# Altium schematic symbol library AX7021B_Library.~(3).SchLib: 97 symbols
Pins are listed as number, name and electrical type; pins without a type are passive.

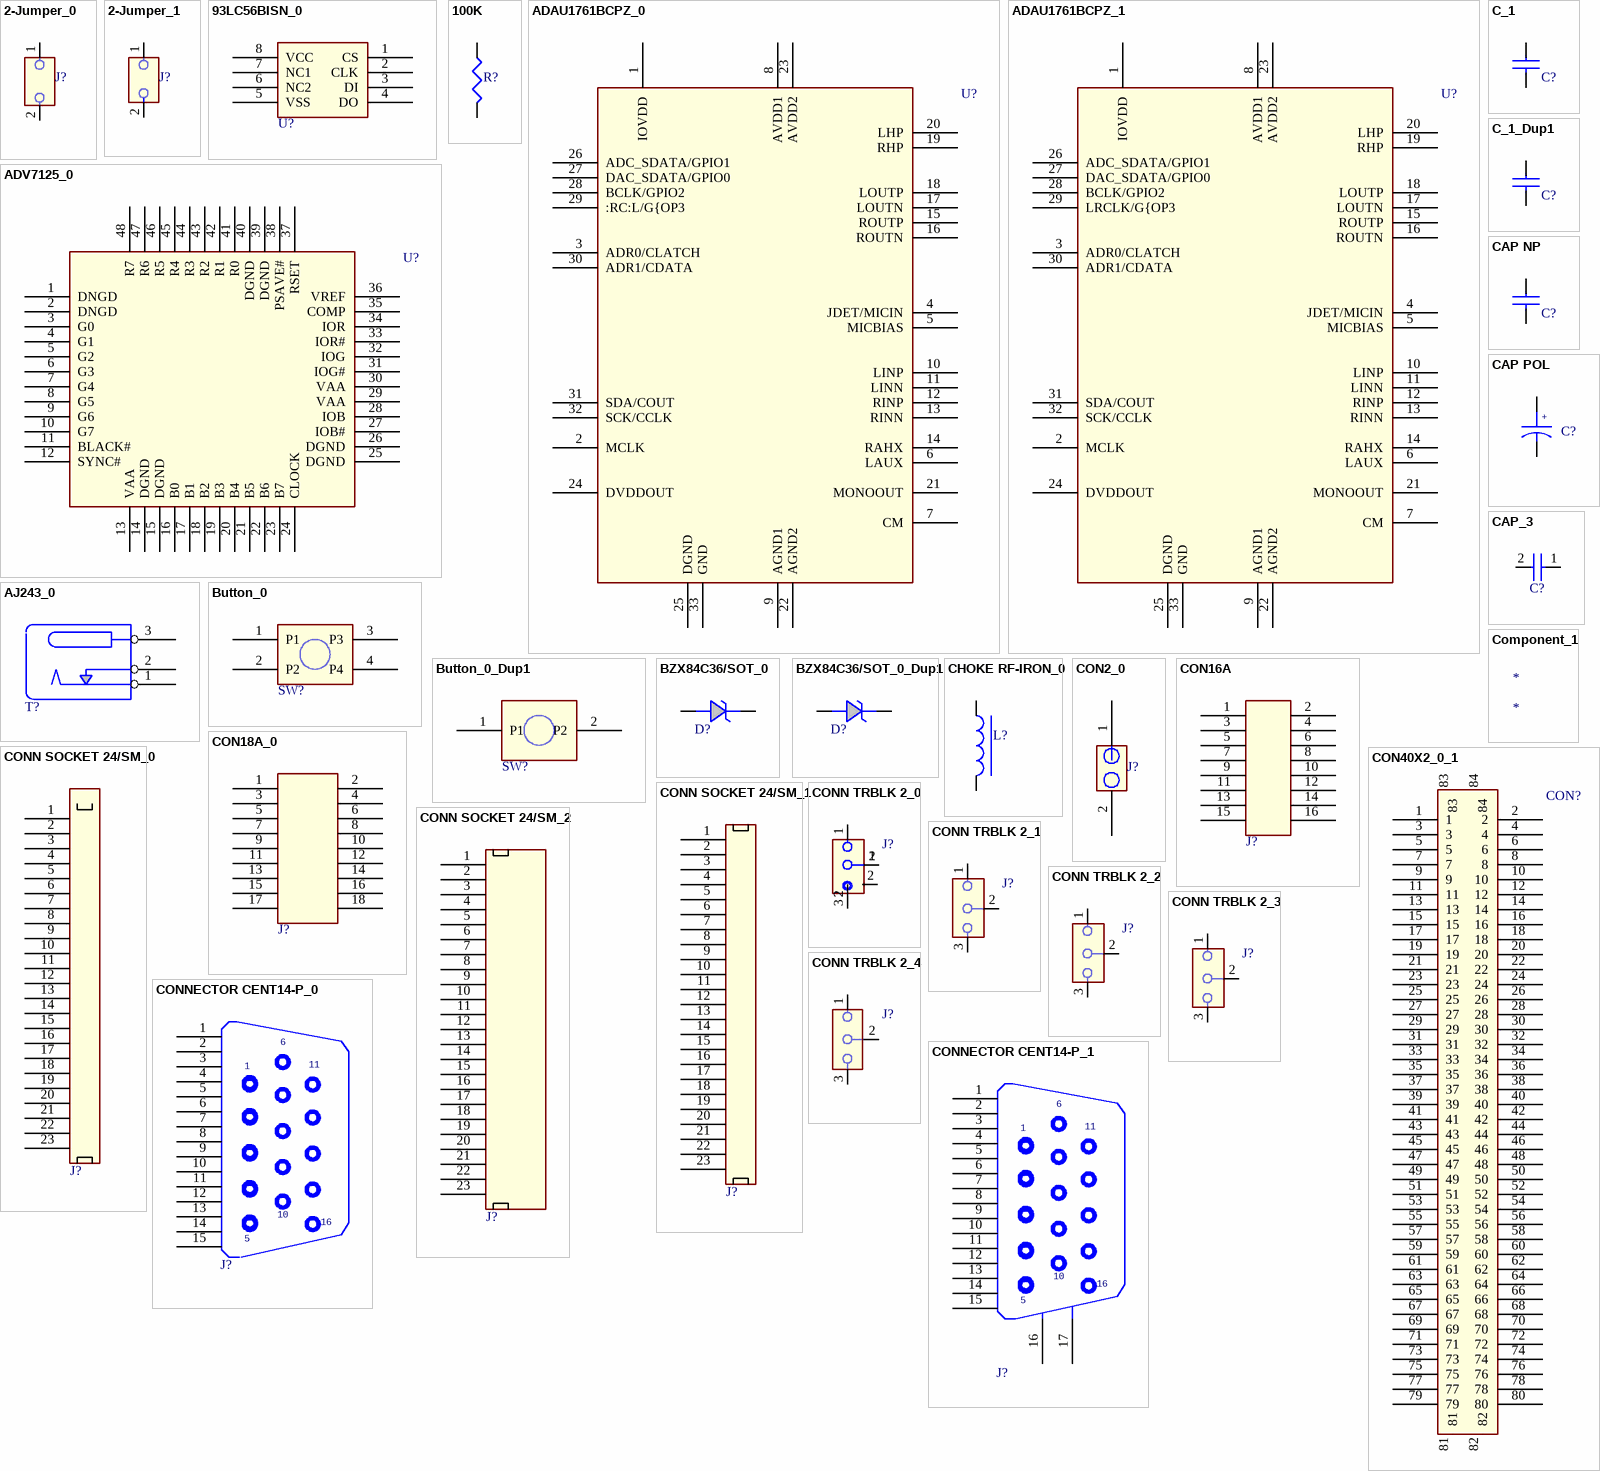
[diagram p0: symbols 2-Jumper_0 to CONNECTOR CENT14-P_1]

## 2-Jumper_0
designator J?
Altium-Right: 20; Altium-Bottom: 32
footprint 2-Jumper
pins: 1, 2

## 2-Jumper_1
designator J?
Altium-Right: 20; Altium-Bottom: 30
footprint 2-Jumper
pins: 1, 2

## 93LC56BISN_0
designator U?
Altium-Right: 60; Altium-Bottom: 50
pins: 1 CS, 2 CLK, 3 DI, 4 DO, 5 VSS, 6 NC2, 7 NC1, 8 VCC

## 100K
designator R?
5%; Part Number: RC0402JR-07100KL; Manufacturer: YAGEO; Altium-Right: 20; Altium-Bottom: 30
footprint R0402
pins: 1, 2

## ADAU1761BCPZ_0
designator U?
Altium-Right: 210; Altium-Bottom: 330
pins: 1 IOVDD, 2 MCLK, 3 ADR0/CLATCH, 4 JDET/MICIN, 5 MICBIAS, 6 LAUX, 7 CM, 8 AVDD1, 9 AGND1, 10 LINP, 11 LINN, 12 RINP, 13 RINN, 14 RAHX, 15 ROUTP, 16 ROUTN, 17 LOUTN, 18 LOUTP, 19 RHP, 20 LHP, 21 MONOOUT, 22 AGND2, 23 AVDD2, 24 DVDDOUT, 25 DGND, 26 ADC_SDATA/GPIO1, 27 DAC_SDATA/GPIO0, 28 BCLK/GPIO2, 29 :RC:L/G{OP3, 30 ADR1/CDATA, 31 SDA/COUT, 32 SCK/CCLK, 33 GND

## ADAU1761BCPZ_1
designator U?
Altium-Right: 210; Altium-Bottom: 330
pins: 1 IOVDD, 2 MCLK, 3 ADR0/CLATCH, 4 JDET/MICIN, 5 MICBIAS, 6 LAUX, 7 CM, 8 AVDD1, 9 AGND1, 10 LINP, 11 LINN, 12 RINP, 13 RINN, 14 RAHX, 15 ROUTP, 16 ROUTN, 17 LOUTN, 18 LOUTP, 19 RHP, 20 LHP, 21 MONOOUT, 22 AGND2, 23 AVDD2, 24 DVDDOUT, 25 DGND, 26 ADC_SDATA/GPIO1, 27 DAC_SDATA/GPIO0, 28 BCLK/GPIO2, 29 LRCLK/G{OP3, 30 ADR1/CDATA, 31 SDA/COUT, 32 SCK/CCLK, 33 GND

## ADV7125_0
designator U?
Altium-Right: 190; Altium-Bottom: 170
footprint LQFP-48
pins: 1 DNGD, 2 DNGD, 3 G0, 4 G1, 5 G2, 6 G3, 7 G4, 8 G5, 9 G6, 10 G7, 11 BLACK#, 12 SYNC#, 13 VAA, 14 DGND, 15 DGND, 16 B0, 17 B1, 18 B2, 19 B3, 20 B4, 21 B5, 22 B6, 23 B7, 24 CLOCK, 25 DGND, 26 DGND, 27 IOB#, 28 IOB, 29 VAA, 30 VAA, 31 IOG#, 32 IOG, 33 IOR#, 34 IOR, 35 COMP, 36 VREF, 37 RSET, 38 PSAVE#, 39 DGND, 40 DGND, 41 R0, 42 R1, 43 R2, 44 R3, 45 R4, 46 R5, 47 R6, 48 R7

## AJ243_0
designator T?
Altium-Right: 70; Altium-Bottom: 50
pins: 1, 2, 3

## Button_0
designator SW?
Altium-Right: 50; Altium-Bottom: 40
pins: 1 P1, 2 P2, 3 P3, 4 P4

## Button_0_Dup1
designator SW?
Altium-Right: 50; Altium-Bottom: 40
pins: 1 P1, 2 P2

## BZX84C36/SOT_0
designator D?
Altium-Right: 30; Altium-Bottom: 20
pins: 1 CATHODE, 2 ANODE

## BZX84C36/SOT_0_Dup1
designator D?
Altium-Right: 30; Altium-Bottom: 20
pins: 1 CATHODE, 2 ANODE

## C_1
designator C?
Altium-Right: 20; Altium-Bottom: 10
pins: 1, 2

## C_1_Dup1
designator C?
Altium-Right: 20; Altium-Bottom: 10
pins: 1, 2

## CAP NP
designator C?
Altium-Right: 20; Altium-Bottom: 10
pins: 1, 2

## CAP POL
designator C?
Altium-Right: 20
pins: 1, 2

## CAP_3
designator C?
Altium-Right: 10; Altium-Bottom: 20
pins: 1, 2

## CHOKE RF-IRON_0
designator L?
Altium-Right: 10; Altium-Bottom: 40
pins: 1, 2

## Component_1
designator *

## CON2_0
designator J?
Altium-Right: 20; Altium-Bottom: 30
pins: 1, 2

## CON16A
designator J?
Altium-Right: 30; Altium-Bottom: 90
pins: 1, 2, 3, 4, 5, 6, 7, 8, 9, 10, 11, 12, 13, 14, 15, 16

## CON18A_0
designator J?
Altium-Right: 40; Altium-Bottom: 100
pins: 1, 2, 3, 4, 5, 6, 7, 8, 9, 10, 11, 12, 13, 14, 15, 16, 17, 18

## CON40X2_0_1
designator CON?
Altium-Right: 40; Altium-Bottom: 430
footprint CON40X2_0_8MM
pins: 1, 2, 3, 4, 5, 6, 7, 8, 9, 10, 11, 12, 13, 14, 15, 16, 17, 18, 19, 20, 21, 22, 23, 24, 25, 26, 27, 28, 29, 30, 31, 32, 33, 34, 35, 36, 37, 38, 39, 40, 41, 42, 43, 44, 45, 46, 47, 48, 49, 50, 51, 52, 53, 54, 55, 56, 57, 58, 59, 60, 61, 62, 63, 64, 65, 66, 67, 68, 69, 70, 71, 72, 73, 74, 75, 76, 77, 78, 79, 80, 81, 82, 83, 84

## CONN SOCKET 24/SM_0
designator J?
Altium-Right: 20; Altium-Bottom: 250
pins: 1, 2, 3, 4, 5, 6, 7, 8, 9, 10, 11, 12, 13, 14, 15, 16, 17, 18, 19, 20, 21, 22, 23

## CONN SOCKET 24/SM_1
designator J?
Altium-Right: 20; Altium-Bottom: 240
pins: 1, 2, 3, 4, 5, 6, 7, 8, 9, 10, 11, 12, 13, 14, 15, 16, 17, 18, 19, 20, 21, 22, 23

## CONN SOCKET 24/SM_2
designator J?
Altium-Right: 40; Altium-Bottom: 240
pins: 1 NC, 2 VSS, 3 VDD, 4 VDDIO, 5 BS1, 6 BS2, 7 IREF, 8 CS#, 9 RES#, 10 D/C#, 11 R/W#, 12 E(RD#), 13 D0, 14 D1, 15 D2, 16 D3, 17 D4, 18 D5, 19 D6, 20 D7, 21 VCOMH, 22 VCC, 23

## CONN TRBLK 2_0
designator J?
Altium-Right: 21; Altium-Bottom: 36
pins: 1, 1, 2, 2, 2, 2, 3

## CONN TRBLK 2_1
designator J?
Altium-Right: 21; Altium-Bottom: 39
pins: 1, 2, 3

## CONN TRBLK 2_2
designator J?
Altium-Right: 21; Altium-Bottom: 39
pins: 1, 2, 3

## CONN TRBLK 2_3
designator J?
Altium-Right: 21; Altium-Bottom: 39
pins: 1, 2, 3

## CONN TRBLK 2_4
designator J?
Altium-Right: 21; Altium-Bottom: 40
pins: 1, 2, 3

## CONNECTOR CENT14-P_0
designator J?
Altium-Right: 86; Altium-Bottom: 157
pins: 1, 2, 3, 4, 5, 6, 7, 8, 9, 10, 11, 12, 13, 14, 15

## CONNECTOR CENT14-P_1
designator J?
Altium-Right: 86; Altium-Bottom: 157
pins: 1, 2, 3, 4, 5, 6, 7, 8, 9, 10, 11, 12, 13, 14, 15, 16, 17

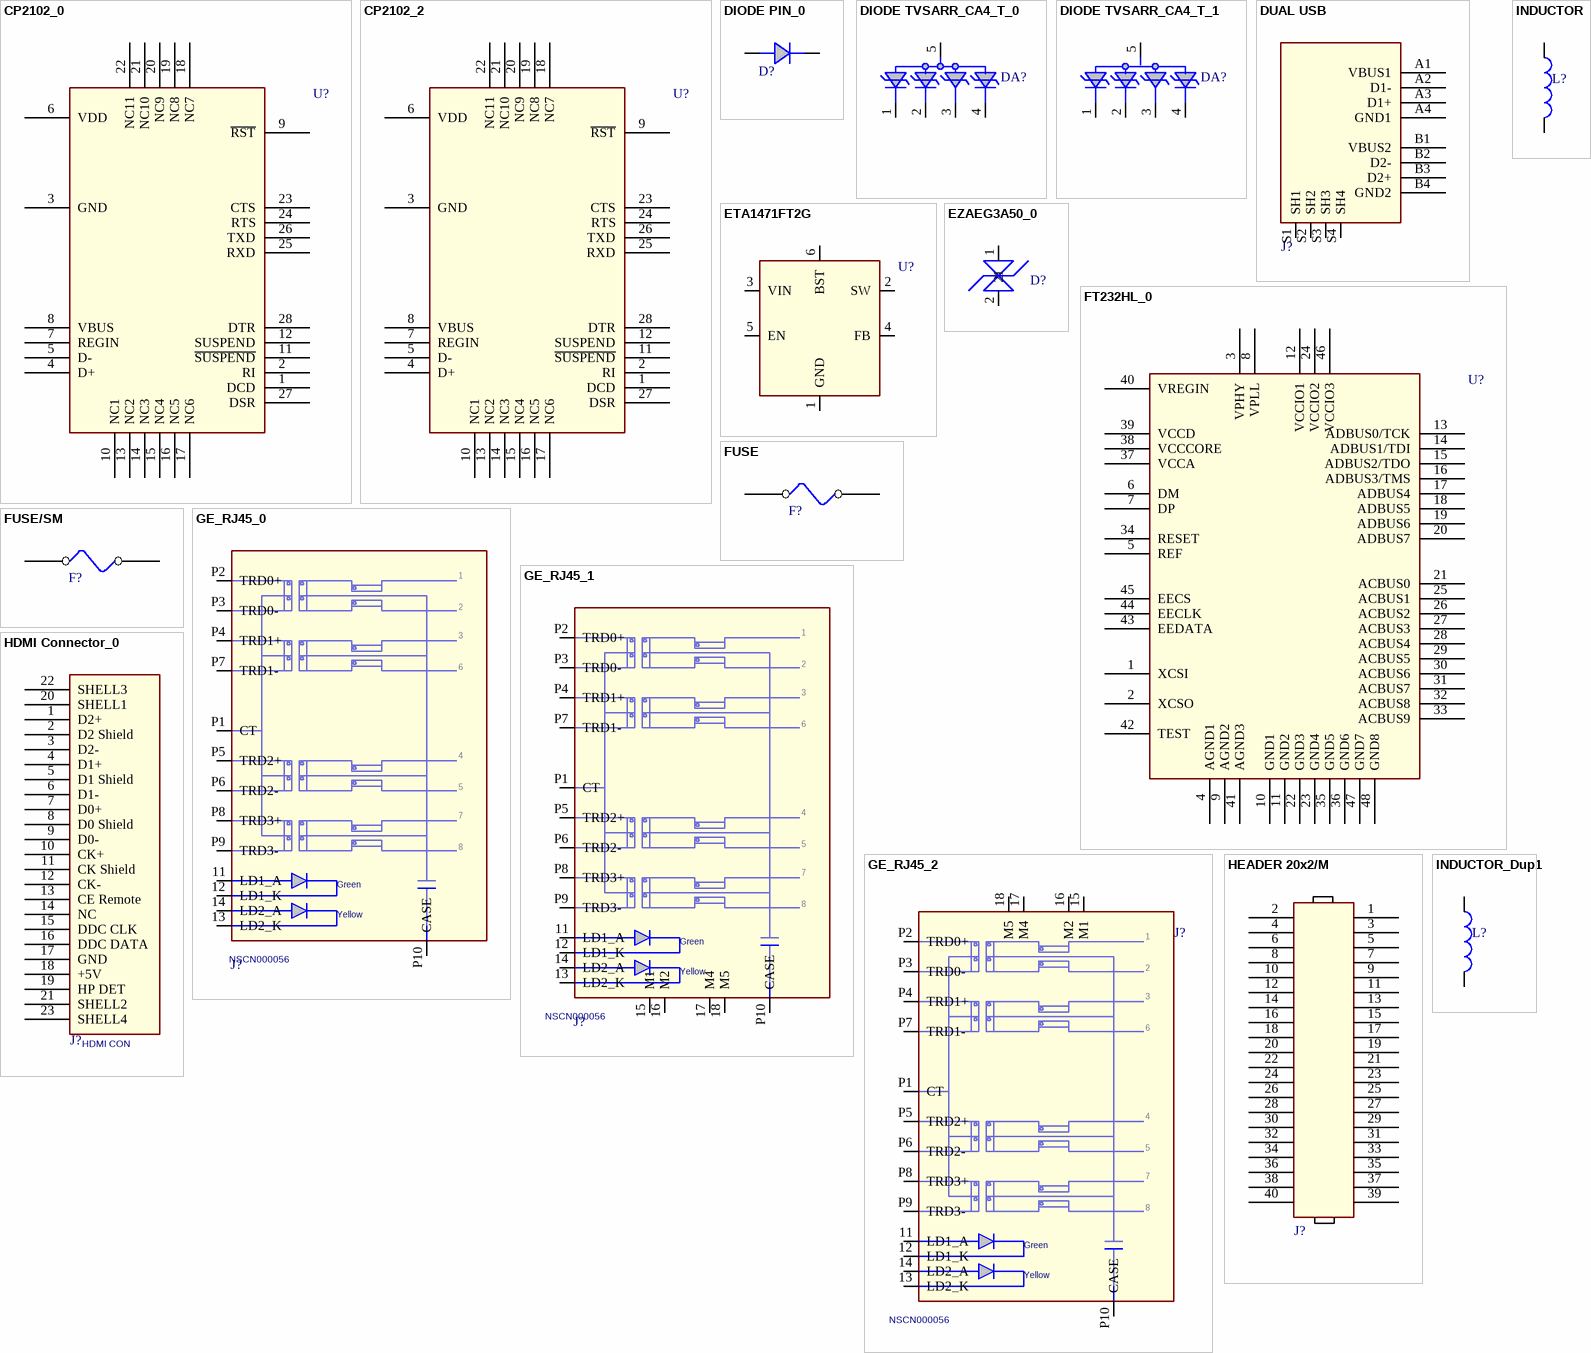
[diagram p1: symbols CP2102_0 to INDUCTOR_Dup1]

## CP2102_0
designator U?
Altium-Right: 130; Altium-Bottom: 230
pins: 1 DCD, 2 RI, 3 GND (power), 4 D+, 5 D-, 6 VDD (power), 7 REGIN, 8 VBUS, 9 ~{RST}, 10 NC1, 11 ~{SUSPEND}, 12 SUSPEND, 13 NC2, 14 NC3, 15 NC4, 16 NC5, 17 NC6, 18 NC7, 19 NC8, 20 NC9, 21 NC10, 22 NC11, 23 CTS, 24 RTS, 25 RXD, 26 TXD, 27 DSR, 28 DTR

## CP2102_2
designator U?
Altium-Right: 130; Altium-Bottom: 230
pins: 1 DCD, 2 RI, 3 GND (power), 4 D+, 5 D-, 6 VDD (power), 7 REGIN, 8 VBUS, 9 ~{RST}, 10 NC1, 11 ~{SUSPEND}, 12 SUSPEND, 13 NC2, 14 NC3, 15 NC4, 16 NC5, 17 NC6, 18 NC7, 19 NC8, 20 NC9, 21 NC10, 22 NC11, 23 CTS, 24 RTS, 25 RXD, 26 TXD, 27 DSR, 28 DTR, 29 EPAD1 (power) hidden to EPAD1, 30 EPAD2 (power) hidden to EPAD2

## DIODE PIN_0
designator D?
Altium-Right: 30; Altium-Bottom: 20
pins: 1, 2

## DIODE TVSARR_CA4_T_0
designator DA?
Altium-Right: 83; Altium-Bottom: 30
pins: 1, 2, 3, 4, 5 GND

## DIODE TVSARR_CA4_T_1
designator DA?
Altium-Right: 83; Altium-Bottom: 30
pins: 1, 2, 3, 4, 5 GND

## DUAL USB
designator J?
Altium-Right: 80; Altium-Bottom: 120
footprint DUAL_USB
pins: A1 VBUS1, A2 D1-, A3 D1+, A4 GND1, B1 VBUS2, B2 D2-, B3 D2+, B4 GND2, S1 SH1 (power), S2 SH2 (power), S3 SH3 (power), S4 SH4 (power)

## ETA1471FT2G
designator U?
Altium-Right: 80; Altium-Bottom: 90
footprint FCTSOT23-6
pins: 1 GND, 2 SW, 3 VIN, 4 FB, 5 EN, 6 BST

## EZAEG3A50_0
designator D?
Altium-Right: 40; Altium-Bottom: 20
footprint D0603
pins: 1, 2

## FT232HL_0
designator U?
Altium-Right: 180; Altium-Bottom: 270
pins: 1 XCSI, 2 XCSO, 3 VPHY, 4 AGND1, 5 REF, 6 DM, 7 DP, 8 VPLL, 9 AGND2, 10 GND1, 11 GND2, 12 VCCIO1, 13 ADBUS0/TCK, 14 ADBUS1/TDI, 15 ADBUS2/TDO, 16 ADBUS3/TMS, 17 ADBUS4, 18 ADBUS5, 19 ADBUS6, 20 ADBUS7, 21 ACBUS0, 22 GND3, 23 GND4, 24 VCCIO2, 25 ACBUS1, 26 ACBUS2, 27 ACBUS3, 28 ACBUS4, 29 ACBUS5, 30 ACBUS6, 31 ACBUS7, 32 ACBUS8, 33 ACBUS9, 34 RESET, 35 GND5, 36 GND6, 37 VCCA, 38 VCCCORE, 39 VCCD, 40 VREGIN, 41 AGND3, 42 TEST, 43 EEDATA, 44 EECLK, 45 EECS, 46 VCCIO3, 47 GND7, 48 GND8

## FUSE
designator F?
Altium-Right: 30; Altium-Bottom: 20
pins: 1, 2

## FUSE/SM
designator F?
Altium-Right: 30; Altium-Bottom: 20
pins: 1, 2

## GE_RJ45_0
designator J?  CODE: NSCN000056
Altium-Right: 170; Altium-Bottom: 260
footprint GE_RJ45
pins: 11 LD1_A, 12 LD1_K, 13 LD2_K, 14 LD2_A, P1 CT, P2 TRD0+, P3 TRD0-, P4 TRD1+, P5 TRD2+, P6 TRD2-, P7 TRD1-, P8 TRD3+, P9 TRD3-, P10 CASE

## GE_RJ45_1
designator J?  CODE: NSCN000056
Altium-Right: 170; Altium-Bottom: 260
footprint GE_RJ45
pins: 11 LD1_A, 12 LD1_K, 13 LD2_K, 14 LD2_A, 15 M1, 16 M2, 17 M4, 18 M5, P1 CT, P2 TRD0+, P3 TRD0-, P4 TRD1+, P5 TRD2+, P6 TRD2-, P7 TRD1-, P8 TRD3+, P9 TRD3-, P10 CASE

## GE_RJ45_2
designator J?  CODE: NSCN000056
Altium-Right: 170; Altium-Bottom: 260
footprint GE_RJ45
pins: 11 LD1_A, 12 LD1_K, 13 LD2_K, 14 LD2_A, 15 M1, 16 M2, 17 M4, 18 M5, P1 CT, P2 TRD0+, P3 TRD0-, P4 TRD1+, P5 TRD2+, P6 TRD2-, P7 TRD1-, P8 TRD3+, P9 TRD3-, P10 CASE

## HDMI Connector_0
designator J?, comment HDMI CON
HDMI connector; 04 MPN: SD-500254-001; Vendor P/N: xxxx-xxxx; MFG: JAE xxxx-xxx; Vendor: JAE; 02 DESC: CONN, HDMI connector R/A; 03 MAN: MOLEX; Altium-Right: 60; Altium-Bottom: 240
footprint SMT
pins: 1 D2+, 2 D2 Shield, 3 D2-, 4 D1+, 5 D1 Shield, 6 D1-, 7 D0+, 8 D0 Shield, 9 D0-, 10 CK+, 11 CK Shield, 12 CK-, 13 CE Remote, 14 NC, 15 DDC CLK, 16 DDC DATA, 17 GND, 18 +5V, 19 HP DET, 20 SHELL1, 21 SHELL2, 22 SHELL3, 23 SHELL4

## HEADER 20x2/M
designator J?
Altium-Right: 40; Altium-Bottom: 230
pins: 1, 2, 3, 4, 5, 6, 7, 8, 9, 10, 11, 12, 13, 14, 15, 16, 17, 18, 19, 20, 21, 22, 23, 24, 25, 26, 27, 28, 29, 30, 31, 32, 33, 34, 35, 36, 37, 38, 39, 40

## INDUCTOR
designator L?
Altium-Right: 10; Altium-Bottom: 40
pins: 1, 2

## INDUCTOR_Dup1
designator L?
Altium-Right: 10; Altium-Bottom: 40
pins: 1, 2

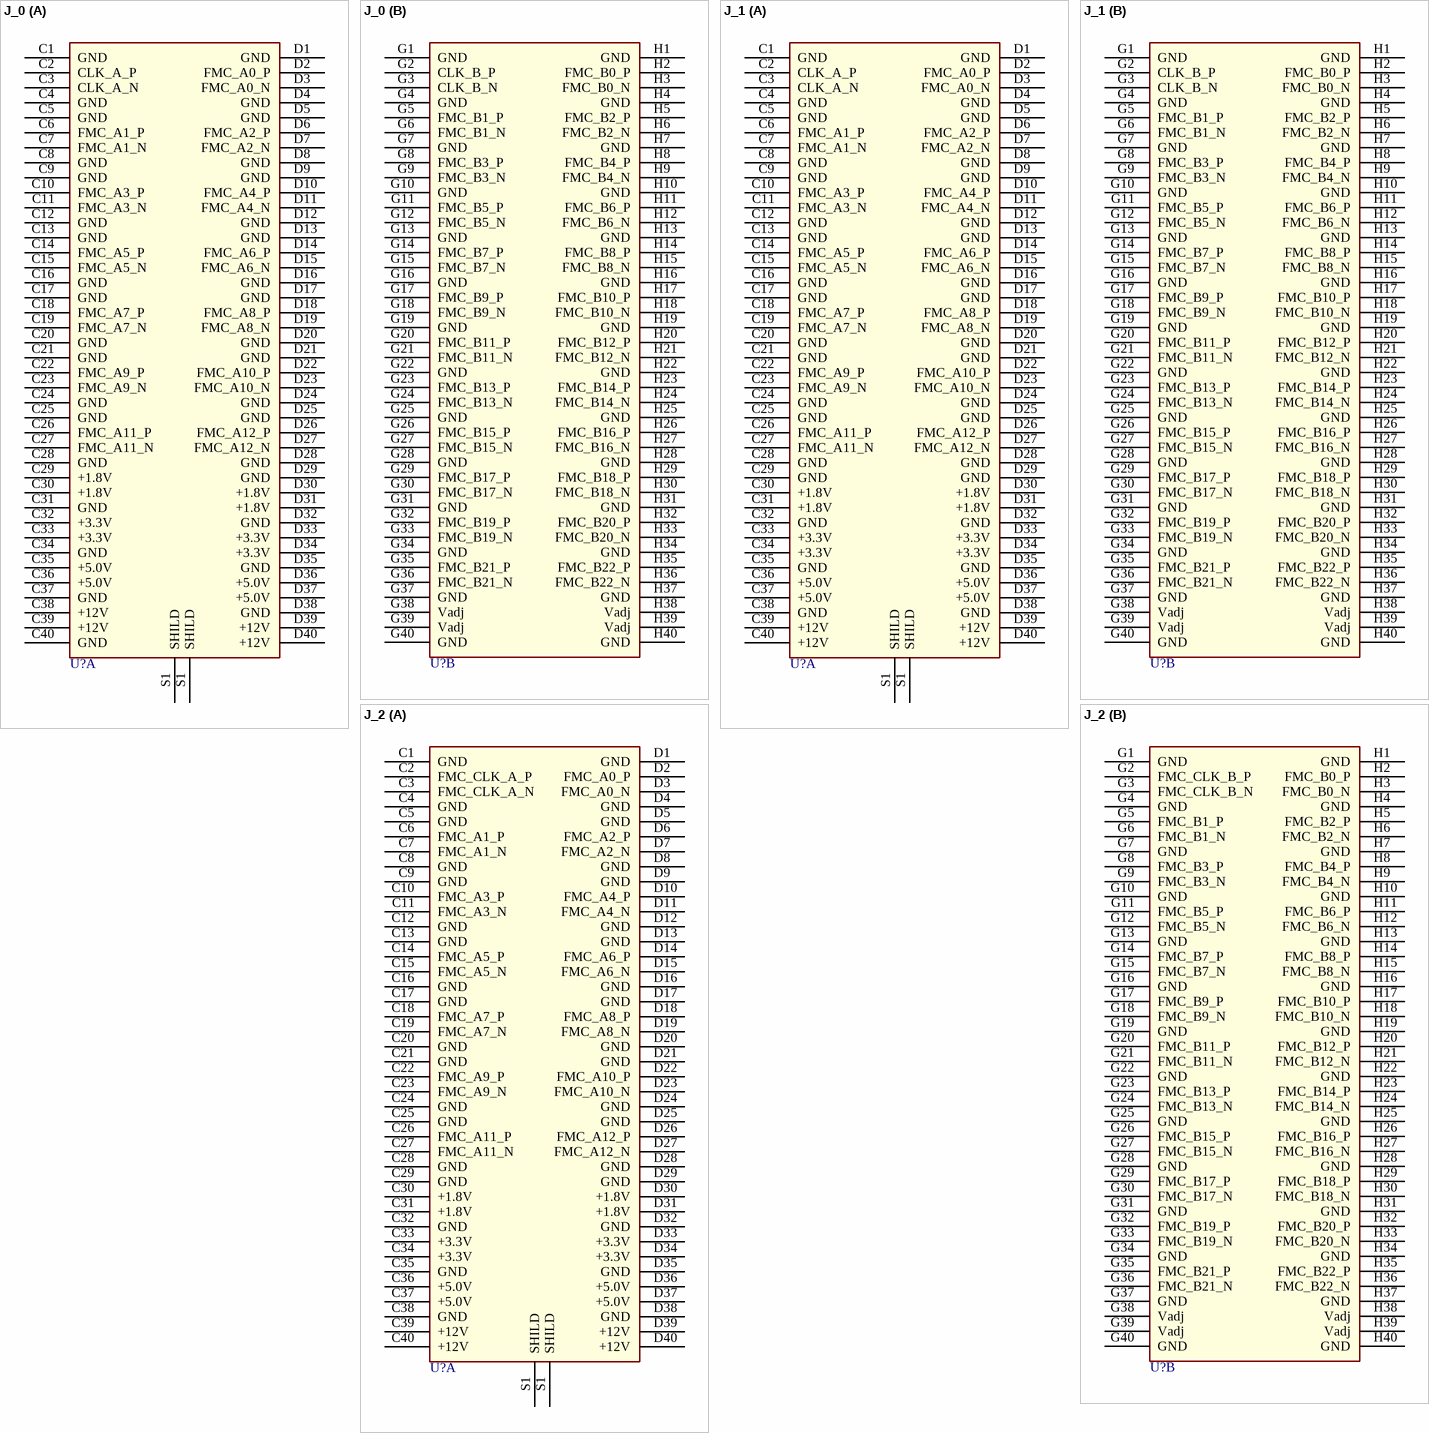
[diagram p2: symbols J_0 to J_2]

## J_0
designator U?
Altium-Right: 140; Altium-Bottom: 410
footprint FMC_CON
part A pins: C1 GND, C2 CLK_A_P, C3 CLK_A_N, C4 GND, C5 GND, C6 FMC_A1_P, C7 FMC_A1_N, C8 GND, C9 GND, C10 FMC_A3_P, C11 FMC_A3_N, C12 GND, C13 GND, C14 FMC_A5_P, C15 FMC_A5_N, C16 GND, C17 GND, C18 FMC_A7_P, C19 FMC_A7_N, C20 GND, C21 GND, C22 FMC_A9_P, C23 FMC_A9_N, C24 GND, C25 GND, C26 FMC_A11_P, C27 FMC_A11_N, C28 GND, C29 +1.8V, C30 +1.8V, C31 GND, C32 +3.3V, C33 +3.3V, C34 GND, C35 +5.0V, C36 +5.0V, C37 GND, C38 +12V, C39 +12V, C40 GND, D1 GND, D2 FMC_A0_P, D3 FMC_A0_N, D4 GND, D5 GND, D6 FMC_A2_P, D7 FMC_A2_N, D8 GND, D9 GND, D10 FMC_A4_P, D11 FMC_A4_N, D12 GND, D13 GND, D14 FMC_A6_P, D15 FMC_A6_N, D16 GND, D17 GND, D18 FMC_A8_P, D19 FMC_A8_N, D20 GND, D21 GND, D22 FMC_A10_P, D23 FMC_A10_N, D24 GND, D25 GND, D26 FMC_A12_P, D27 FMC_A12_N, D28 GND, D29 GND, D30 +1.8V, D31 +1.8V, D32 GND, D33 +3.3V, D34 +3.3V, D35 GND, D36 +5.0V, D37 +5.0V, D38 GND, D39 +12V, D40 +12V, S1 SHILD, S1 SHILD
part B pins: G1 GND, G2 CLK_B_P, G3 CLK_B_N, G4 GND, G5 FMC_B1_P, G6 FMC_B1_N, G7 GND, G8 FMC_B3_P, G9 FMC_B3_N, G10 GND, G11 FMC_B5_P, G12 FMC_B5_N, G13 GND, G14 FMC_B7_P, G15 FMC_B7_N, G16 GND, G17 FMC_B9_P, G18 FMC_B9_N, G19 GND, G20 FMC_B11_P, G21 FMC_B11_N, G22 GND, G23 FMC_B13_P, G24 FMC_B13_N, G25 GND, G26 FMC_B15_P, G27 FMC_B15_N, G28 GND, G29 FMC_B17_P, G30 FMC_B17_N, G31 GND, G32 FMC_B19_P, G33 FMC_B19_N, G34 GND, G35 FMC_B21_P, G36 FMC_B21_N, G37 GND, G38 Vadj, G39 Vadj, G40 GND, H1 GND, H2 FMC_B0_P, H3 FMC_B0_N, H4 GND, H5 FMC_B2_P, H6 FMC_B2_N, H7 GND, H8 FMC_B4_P, H9 FMC_B4_N, H10 GND, H11 FMC_B6_P, H12 FMC_B6_N, H13 GND, H14 FMC_B8_P, H15 FMC_B8_N, H16 GND, H17 FMC_B10_P, H18 FMC_B10_N, H19 GND, H20 FMC_B12_P, H21 FMC_B12_N, H22 GND, H23 FMC_B14_P, H24 FMC_B14_N, H25 GND, H26 FMC_B16_P, H27 FMC_B16_N, H28 GND, H29 FMC_B18_P, H30 FMC_B18_N, H31 GND, H32 FMC_B20_P, H33 FMC_B20_N, H34 GND, H35 FMC_B22_P, H36 FMC_B22_N, H37 GND, H38 Vadj, H39 Vadj, H40 GND

## J_1
designator U?
Altium-Right: 140; Altium-Bottom: 410
footprint FMC_CON
part A pins: C1 GND, C2 CLK_A_P, C3 CLK_A_N, C4 GND, C5 GND, C6 FMC_A1_P, C7 FMC_A1_N, C8 GND, C9 GND, C10 FMC_A3_P, C11 FMC_A3_N, C12 GND, C13 GND, C14 FMC_A5_P, C15 FMC_A5_N, C16 GND, C17 GND, C18 FMC_A7_P, C19 FMC_A7_N, C20 GND, C21 GND, C22 FMC_A9_P, C23 FMC_A9_N, C24 GND, C25 GND, C26 FMC_A11_P, C27 FMC_A11_N, C28 GND, C29 GND, C30 +1.8V, C31 +1.8V, C32 GND, C33 +3.3V, C34 +3.3V, C35 GND, C36 +5.0V, C37 +5.0V, C38 GND, C39 +12V, C40 +12V, D1 GND, D2 FMC_A0_P, D3 FMC_A0_N, D4 GND, D5 GND, D6 FMC_A2_P, D7 FMC_A2_N, D8 GND, D9 GND, D10 FMC_A4_P, D11 FMC_A4_N, D12 GND, D13 GND, D14 FMC_A6_P, D15 FMC_A6_N, D16 GND, D17 GND, D18 FMC_A8_P, D19 FMC_A8_N, D20 GND, D21 GND, D22 FMC_A10_P, D23 FMC_A10_N, D24 GND, D25 GND, D26 FMC_A12_P, D27 FMC_A12_N, D28 GND, D29 GND, D30 +1.8V, D31 +1.8V, D32 GND, D33 +3.3V, D34 +3.3V, D35 GND, D36 +5.0V, D37 +5.0V, D38 GND, D39 +12V, D40 +12V, S1 SHILD, S1 SHILD
part B pins: G1 GND, G2 CLK_B_P, G3 CLK_B_N, G4 GND, G5 FMC_B1_P, G6 FMC_B1_N, G7 GND, G8 FMC_B3_P, G9 FMC_B3_N, G10 GND, G11 FMC_B5_P, G12 FMC_B5_N, G13 GND, G14 FMC_B7_P, G15 FMC_B7_N, G16 GND, G17 FMC_B9_P, G18 FMC_B9_N, G19 GND, G20 FMC_B11_P, G21 FMC_B11_N, G22 GND, G23 FMC_B13_P, G24 FMC_B13_N, G25 GND, G26 FMC_B15_P, G27 FMC_B15_N, G28 GND, G29 FMC_B17_P, G30 FMC_B17_N, G31 GND, G32 FMC_B19_P, G33 FMC_B19_N, G34 GND, G35 FMC_B21_P, G36 FMC_B21_N, G37 GND, G38 Vadj, G39 Vadj, G40 GND, H1 GND, H2 FMC_B0_P, H3 FMC_B0_N, H4 GND, H5 FMC_B2_P, H6 FMC_B2_N, H7 GND, H8 FMC_B4_P, H9 FMC_B4_N, H10 GND, H11 FMC_B6_P, H12 FMC_B6_N, H13 GND, H14 FMC_B8_P, H15 FMC_B8_N, H16 GND, H17 FMC_B10_P, H18 FMC_B10_N, H19 GND, H20 FMC_B12_P, H21 FMC_B12_N, H22 GND, H23 FMC_B14_P, H24 FMC_B14_N, H25 GND, H26 FMC_B16_P, H27 FMC_B16_N, H28 GND, H29 FMC_B18_P, H30 FMC_B18_N, H31 GND, H32 FMC_B20_P, H33 FMC_B20_N, H34 GND, H35 FMC_B22_P, H36 FMC_B22_N, H37 GND, H38 Vadj, H39 Vadj, H40 GND

## J_2
designator U?
Altium-Right: 140; Altium-Bottom: 410
footprint FMC_CON
part A pins: C1 GND, C2 FMC_CLK_A_P, C3 FMC_CLK_A_N, C4 GND, C5 GND, C6 FMC_A1_P, C7 FMC_A1_N, C8 GND, C9 GND, C10 FMC_A3_P, C11 FMC_A3_N, C12 GND, C13 GND, C14 FMC_A5_P, C15 FMC_A5_N, C16 GND, C17 GND, C18 FMC_A7_P, C19 FMC_A7_N, C20 GND, C21 GND, C22 FMC_A9_P, C23 FMC_A9_N, C24 GND, C25 GND, C26 FMC_A11_P, C27 FMC_A11_N, C28 GND, C29 GND, C30 +1.8V, C31 +1.8V, C32 GND, C33 +3.3V, C34 +3.3V, C35 GND, C36 +5.0V, C37 +5.0V, C38 GND, C39 +12V, C40 +12V, D1 GND, D2 FMC_A0_P, D3 FMC_A0_N, D4 GND, D5 GND, D6 FMC_A2_P, D7 FMC_A2_N, D8 GND, D9 GND, D10 FMC_A4_P, D11 FMC_A4_N, D12 GND, D13 GND, D14 FMC_A6_P, D15 FMC_A6_N, D16 GND, D17 GND, D18 FMC_A8_P, D19 FMC_A8_N, D20 GND, D21 GND, D22 FMC_A10_P, D23 FMC_A10_N, D24 GND, D25 GND, D26 FMC_A12_P, D27 FMC_A12_N, D28 GND, D29 GND, D30 +1.8V, D31 +1.8V, D32 GND, D33 +3.3V, D34 +3.3V, D35 GND, D36 +5.0V, D37 +5.0V, D38 GND, D39 +12V, D40 +12V, S1 SHILD, S1 SHILD
part B pins: G1 GND, G2 FMC_CLK_B_P, G3 FMC_CLK_B_N, G4 GND, G5 FMC_B1_P, G6 FMC_B1_N, G7 GND, G8 FMC_B3_P, G9 FMC_B3_N, G10 GND, G11 FMC_B5_P, G12 FMC_B5_N, G13 GND, G14 FMC_B7_P, G15 FMC_B7_N, G16 GND, G17 FMC_B9_P, G18 FMC_B9_N, G19 GND, G20 FMC_B11_P, G21 FMC_B11_N, G22 GND, G23 FMC_B13_P, G24 FMC_B13_N, G25 GND, G26 FMC_B15_P, G27 FMC_B15_N, G28 GND, G29 FMC_B17_P, G30 FMC_B17_N, G31 GND, G32 FMC_B19_P, G33 FMC_B19_N, G34 GND, G35 FMC_B21_P, G36 FMC_B21_N, G37 GND, G38 Vadj, G39 Vadj, G40 GND, H1 GND, H2 FMC_B0_P, H3 FMC_B0_N, H4 GND, H5 FMC_B2_P, H6 FMC_B2_N, H7 GND, H8 FMC_B4_P, H9 FMC_B4_N, H10 GND, H11 FMC_B6_P, H12 FMC_B6_N, H13 GND, H14 FMC_B8_P, H15 FMC_B8_N, H16 GND, H17 FMC_B10_P, H18 FMC_B10_N, H19 GND, H20 FMC_B12_P, H21 FMC_B12_N, H22 GND, H23 FMC_B14_P, H24 FMC_B14_N, H25 GND, H26 FMC_B16_P, H27 FMC_B16_N, H28 GND, H29 FMC_B18_P, H30 FMC_B18_N, H31 GND, H32 FMC_B20_P, H33 FMC_B20_N, H34 GND, H35 FMC_B22_P, H36 FMC_B22_N, H37 GND, H38 Vadj, H39 Vadj, H40 GND

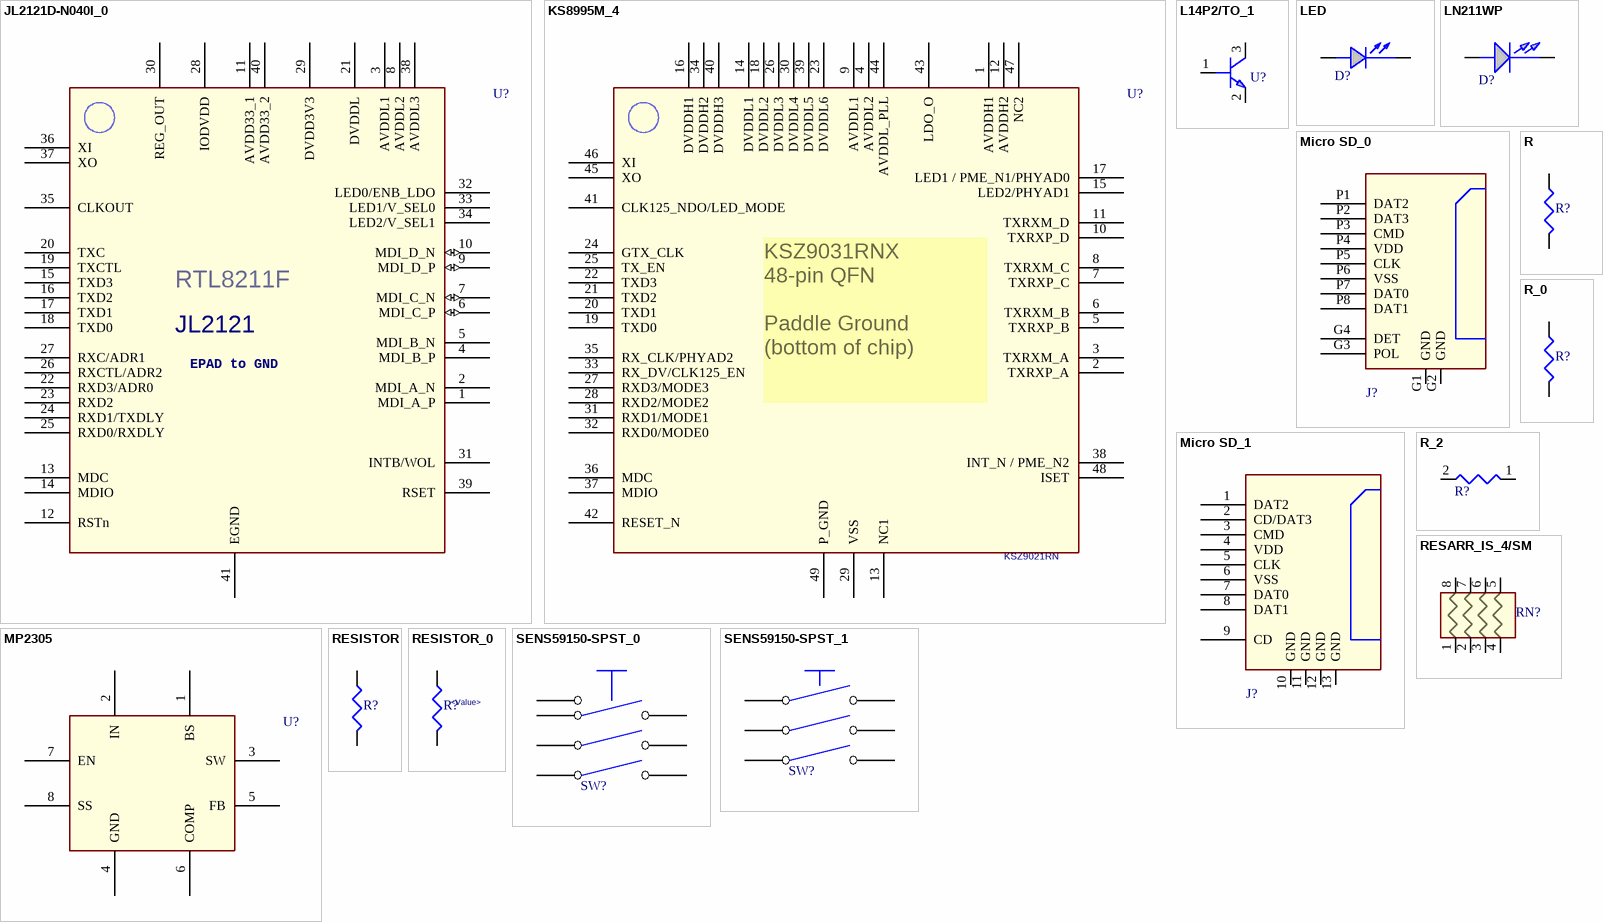
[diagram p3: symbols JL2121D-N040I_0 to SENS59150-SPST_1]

## JL2121D-N040I_0
designator U?, comment 8169SB  (value not drawn)
Altium-Right: 250; Altium-Bottom: 310
footprint QFN40
pins: 1 MDI_A_P, 2 MDI_A_N, 3 AVDDL1, 4 MDI_B_P, 5 MDI_B_N, 6 MDI_C_P (io), 7 MDI_C_N (io), 8 AVDDL2, 9 MDI_D_P (io), 10 MDI_D_N (io), 11 AVDD33_1 (power), 12 RSTn, 13 MDC, 14 MDIO, 15 TXD3, 16 TXD2 (power), 17 TXD1, 18 TXD0, 19 TXCTL, 20 TXC, 21 DVDDL (power), 22 RXD3/ADR0, 23 RXD2, 24 RXD1/TXDLY, 25 RXD0/RXDLY, 26 RXCTL/ADR2, 27 RXC/ADR1, 28 IODVDD (power), 29 DVDD3V3 (power), 30 REG_OUT (power), 31 INTB/WOL, 32 LED0/ENB_LDO, 33 LED1/V_SEL0, 34 LED2/V_SEL1, 35 CLKOUT, 36 XI, 37 XO, 38 AVDDL3 (power), 39 RSET, 40 AVDD33_2, 41 EGND (power)

## KS8995M_4
designator U?, comment KSZ9021RN
Altium-Right: 310
pins: 1 AVDDH1, 2 TXRXP_A, 3 TXRXM_A, 4 AVDDL2, 5 TXRXP_B, 6 TXRXM_B, 7 TXRXP_C, 8 TXRXM_C, 9 AVDDL1, 10 TXRXP_D, 11 TXRXM_D, 12 AVDDH2, 13 NC1, 14 DVDDL1, 15 LED2/PHYAD1, 16 DVDDH1, 17 LED1 / PME_N1/PHYAD0, 18 DVDDL2, 19 TXD0, 20 TXD1, 21 TXD2, 22 TXD3, 23 DVDDL6, 24 GTX_CLK, 25 TX_EN, 26 DVDDL3, 27 RXD3/MODE3, 28 RXD2/MODE2, 29 VSS, 30 DVDDL4, 31 RXD1/MODE1, 32 RXD0/MODE0, 33 RX_DV/CLK125_EN, 34 DVDDH2, 35 RX_CLK/PHYAD2, 36 MDC, 37 MDIO, 38 INT_N / PME_N2, 39 DVDDL5, 40 DVDDH3, 41 CLK125_NDO/LED_MODE, 42 RESET_N, 43 LDO_O, 44 AVDDL_PLL, 45 XO, 46 XI, 47 NC2, 48 ISET, 49 P_GND

## L14P2/TO_1
designator U?
Altium-Right: 20
pins: 1 BASE, 2 EMITTER, 3 COLLECTOR

## LED
designator D?
Altium-Right: 40; Altium-Bottom: 20
pins: 1 ANODE, 2 CATHODE

## LN211WP
designator D?
Altium-Right: 40; Altium-Bottom: 20
pins: 1 ANODE, 2 CATHODE

## Micro SD_0
designator J?
Altium-Right: 80; Altium-Bottom: 130
footprint Micro_usb
pins: G1 GND (power), G2 GND (power), G3 POL, G4 DET, P1 DAT2, P2 DAT3, P3 CMD, P4 VDD (power), P5 CLK, P6 VSS (power), P7 DAT0, P8 DAT1

## Micro SD_1
designator J?
Altium-Right: 90; Altium-Bottom: 130
footprint Micro_usb
pins: 1 DAT2, 2 CD/DAT3, 3 CMD, 4 VDD (power), 5 CLK, 6 VSS (power), 7 DAT0, 8 DAT1, 9 CD, 10 GND (power), 11 GND (power), 12 GND (power), 13 GND (power)

## MP2305
designator U?
Altium-Right: 110; Altium-Bottom: 90
pins: 1 BS, 2 IN, 3 SW, 4 GND, 5 FB, 6 COMP, 7 EN, 8 SS

## R
designator R?
Altium-Right: 20; Altium-Bottom: 30
pins: 1, 2

## R_0
designator R?
Altium-Right: 20; Altium-Bottom: 30
pins: 1, 2

## R_2
designator R?
Altium-Right: 30; Altium-Bottom: 20
pins: 1, 2

## RESARR_IS_4/SM
designator RN?
Altium-Right: 50; Altium-Bottom: 30
pins: 1, 2, 3, 4, 5, 6, 7, 8

## RESISTOR
designator R?
Altium-Right: 20; Altium-Bottom: 30
pins: 1, 2

## RESISTOR_0
designator R?, comment <Value>
Altium-Right: 20; Altium-Bottom: 30
pins: 1, 2

## SENS59150-SPST_0
designator SW?
Altium-Right: 40; Altium-Bottom: 80
pins: 1, 1, 1, 2, 3, 4, 5, 6

## SENS59150-SPST_1
designator SW?
Altium-Right: 40; Altium-Bottom: 70
pins: 1, 2, 3, 4, 5, 6

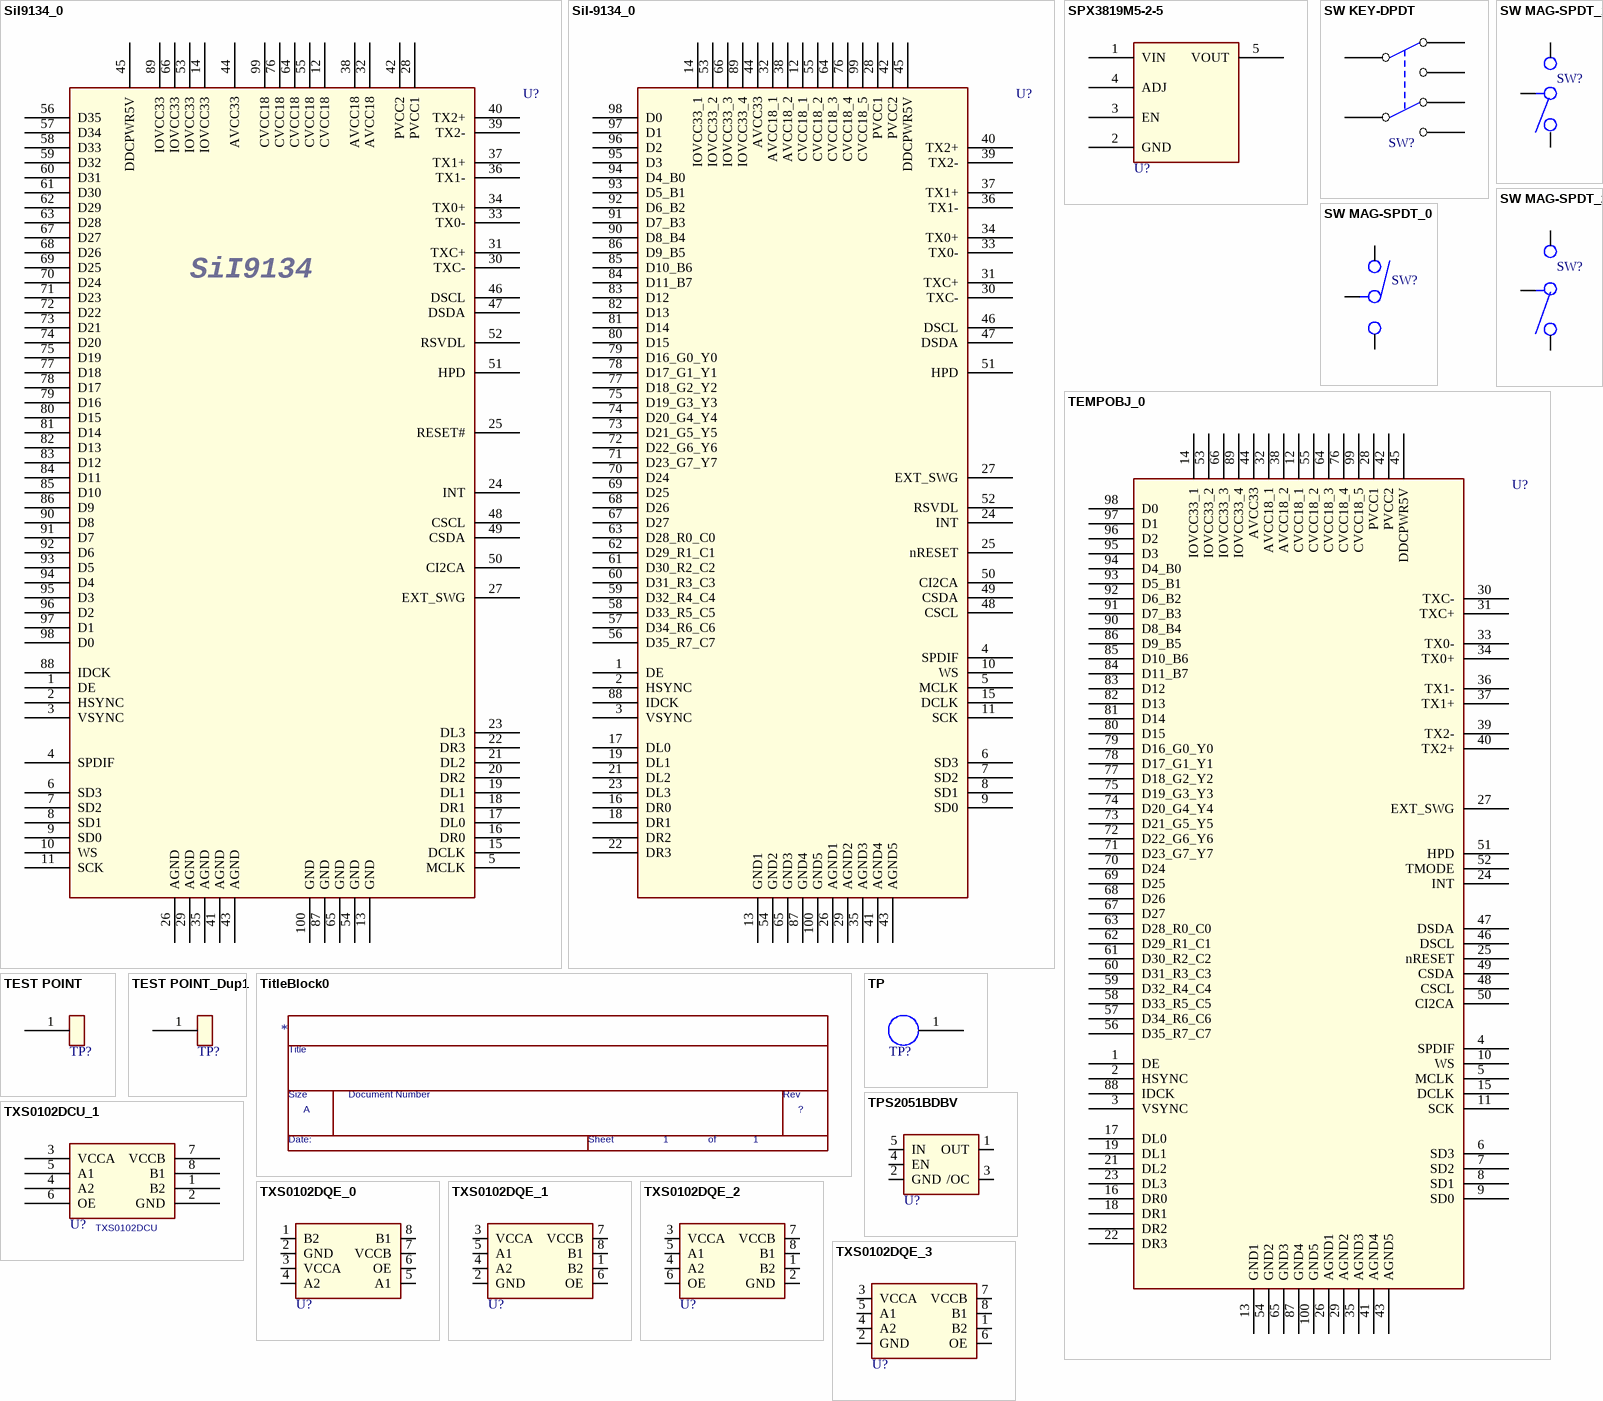
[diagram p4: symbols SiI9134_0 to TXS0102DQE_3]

## SiI9134_0
designator U?
Altium-Right: 270; Altium-Bottom: 540
pins: 1 DE, 2 HSYNC, 3 VSYNC, 4 SPDIF, 5 MCLK, 6 SD3, 7 SD2, 8 SD1, 9 SD0, 10 WS, 11 SCK, 12 CVCC18 (power), 13 GND (power), 14 IOVCC33 (power), 15 DCLK, 16 DR0, 17 DL0, 18 DR1, 19 DL1, 20 DR2, 21 DL2, 22 DR3, 23 DL3, 24 INT, 25 RESET#, 26 AGND (power), 27 EXT_SWG, 28 PVCC1 (power), 29 AGND (power), 30 TXC-, 31 TXC+, 32 AVCC18 (power), 33 TX0-, 34 TX0+, 35 AGND (power), 36 TX1-, 37 TX1+, 38 AVCC18 (power), 39 TX2-, 40 TX2+, 41 AGND (power), 42 PVCC2 (power), 43 AGND (power), 44 AVCC33 (power), 45 DDCPWR5V (power), 46 DSCL, 47 DSDA, 48 CSCL, 49 CSDA, 50 CI2CA, 51 HPD, 52 RSVDL, 53 IOVCC33 (power), 54 GND (power), 55 CVCC18 (power), 56 D35, 57 D34, 58 D33, 59 D32, 60 D31, 61 D30, 62 D29, 63 D28, 64 CVCC18 (power), 65 GND (power), 66 IOVCC33 (power), 67 D27, 68 D26, 69 D25, 70 D24, 71 D23, 72 D22, 73 D21, 74 D20, 75 D19, 76 CVCC18 (power), 77 D18, 78 D17, 79 D16, 80 D15, 81 D14, 82 D13, 83 D12, 84 D11, 85 D10, 86 D9, 87 GND (power), 88 IDCK, 89 IOVCC33 (power), 90 D8, 91 D7, 92 D6, 93 D5, 94 D4, 95 D3, 96 D2, 97 D1, 98 D0, 99 CVCC18 (power), 100 GND (power)

## SiI-9134_0
designator U?
Altium-Right: 220; Altium-Bottom: 540
pins: 1 DE, 2 HSYNC, 3 VSYNC, 4 SPDIF, 5 MCLK, 6 SD3, 7 SD2, 8 SD1, 9 SD0, 10 WS, 11 SCK, 12 CVCC18_1, 13 GND1, 14 IOVCC33_1, 15 DCLK, 16 DR0, 17 DL0, 18 DR1, 19 DL1, 21 DL2, 22 DR3, 23 DL3, 24 INT, 25 nRESET, 26 AGND1, 27 EXT_SWG, 28 PVCC1, 29 AGND2, 30 TXC-, 31 TXC+, 32 AVCC18_1, 33 TX0-, 34 TX0+, 35 AGND3, 36 TX1-, 37 TX1+, 38 AVCC18_2, 39 TX2-, 40 TX2+, 41 AGND4, 42 PVCC2, 43 AGND5, 44 AVCC33, 45 DDCPWR5V, 46 DSCL, 47 DSDA, 48 CSCL, 49 CSDA, 50 CI2CA, 51 HPD, 52 RSVDL, 53 IOVCC33_2, 54 GND2, 55 CVCC18_2, 56 D35_R7_C7, 57 D34_R6_C6, 58 D33_R5_C5, 59 D32_R4_C4, 60 D31_R3_C3, 61 D30_R2_C2, 62 D29_R1_C1, 63 D28_R0_C0, 64 CVCC18_3, 65 GND3, 66 IOVCC33_3, 67 D27, 68 D26, 69 D25, 70 D24, 71 D23_G7_Y7, 72 D22_G6_Y6, 73 D21_G5_Y5, 74 D20_G4_Y4, 75 D19_G3_Y3, 76 CVCC18_4, 77 D18_G2_Y2, 78 D17_G1_Y1, 79 D16_G0_Y0, 80 D15, 81 D14, 82 D13, 83 D12, 84 D11_B7, 85 D10_B6, 86 D9_B5, 87 GND4, 88 IDCK, 89 IOVCC33_4, 90 D8_B4, 91 D7_B3, 92 D6_B2, 93 D5_B1, 94 D4_B0, 95 D3, 96 D2, 97 D1, 98 D0, 99 CVCC18_5, 100 GND5, DR2

## SPX3819M5-2-5
designator U?
Altium-Right: 70; Altium-Bottom: 80
footprint SOT-23
pins: 1 VIN, 2 GND, 3 EN, 4 ADJ, 5 VOUT

## SW KEY-DPDT
designator SW?
Altium-Right: 20; Altium-Bottom: 80
pins: 1 NC1, 2 COMMON1, 3 NO1, 4 NC2, 5 COMMON2, 6 NO2

## SW MAG-SPDT_0
designator SW?
Altium-Right: 20; Altium-Bottom: 49
pins: 1 NC, 2 COMMON, 3 NO

## SW MAG-SPDT_1
designator SW?
Altium-Right: 20; Altium-Bottom: 50
pins: 1 NC, 2 COMMON, 3 NO

## SW MAG-SPDT_2
designator SW?
Altium-Right: 20; Altium-Bottom: 60
pins: 1 NC, 2 COMMON, 3 NO

## TEMPOBJ_0
designator U?
Altium-Right: 220; Altium-Bottom: 540
pins: 1 DE, 2 HSYNC, 3 VSYNC, 4 SPDIF, 5 MCLK, 6 SD3, 7 SD2, 8 SD1, 9 SD0, 10 WS, 11 SCK, 12 CVCC18_1, 13 GND1, 14 IOVCC33_1, 15 DCLK, 16 DR0, 17 DL0, 18 DR1, 19 DL1, 21 DL2, 22 DR3, 23 DL3, 24 INT, 25 nRESET, 26 AGND1, 27 EXT_SWG, 28 PVCC1, 29 AGND2, 30 TXC-, 31 TXC+, 32 AVCC18_1, 33 TX0-, 34 TX0+, 35 AGND3, 36 TX1-, 37 TX1+, 38 AVCC18_2, 39 TX2-, 40 TX2+, 41 AGND4, 42 PVCC2, 43 AGND5, 44 AVCC33, 45 DDCPWR5V, 46 DSCL, 47 DSDA, 48 CSCL, 49 CSDA, 50 CI2CA, 51 HPD, 52 TMODE, 53 IOVCC33_2, 54 GND2, 55 CVCC18_2, 56 D35_R7_C7, 57 D34_R6_C6, 58 D33_R5_C5, 59 D32_R4_C4, 60 D31_R3_C3, 61 D30_R2_C2, 62 D29_R1_C1, 63 D28_R0_C0, 64 CVCC18_3, 65 GND3, 66 IOVCC33_3, 67 D27, 68 D26, 69 D25, 70 D24, 71 D23_G7_Y7, 72 D22_G6_Y6, 73 D21_G5_Y5, 74 D20_G4_Y4, 75 D19_G3_Y3, 76 CVCC18_4, 77 D18_G2_Y2, 78 D17_G1_Y1, 79 D16_G0_Y0, 80 D15, 81 D14, 82 D13, 83 D12, 84 D11_B7, 85 D10_B6, 86 D9_B5, 87 GND4, 88 IDCK, 89 IOVCC33_4, 90 D8_B4, 91 D7_B3, 92 D6_B2, 93 D5_B1, 94 D4_B0, 95 D3, 96 D2, 97 D1, 98 D0, 99 CVCC18_5, 100 GND5, DR2

## TEST POINT
designator TP?
Altium-Right: 10; Altium-Bottom: 20
pins: 1

## TEST POINT_Dup1
designator TP?
Altium-Right: 10; Altium-Bottom: 20
pins: 1

## TitleBlock0
designator *  Page Size: A  Page Number: 1  (graphical)
Altium-Right: 360; Altium-Bottom: 90

## TP
designator TP?
Altium-Right: 20
footprint TP_1-0
pins: 1

## TPS2051BDBV
designator U?
Altium-Right: 50; Altium-Bottom: 40
footprint TPS2051BDBV
pins: 1 OUT, 2 GND, 3 /OC, 4 EN, 5 IN

## TXS0102DCU_1
designator U?, comment TXS0102DCU
Altium-Right: 70; Altium-Bottom: 50
pins: 1 B2, 2 GND, 3 VCCA, 4 A2, 5 A1, 6 OE, 7 VCCB, 8 B1

## TXS0102DQE_0
designator U?
Altium-Right: 70; Altium-Bottom: 50
footprint TXS0102DQE
pins: 1 B2, 2 GND, 3 VCCA, 4 A2, 5 A1, 6 OE, 7 VCCB, 8 B1

## TXS0102DQE_1
designator U?
Altium-Right: 70; Altium-Bottom: 50
footprint TXS0102DQE
pins: 1 B2, 2 GND, 3 VCCA, 4 A2, 5 A1, 6 OE, 7 VCCB, 8 B1

## TXS0102DQE_2
designator U?
Altium-Right: 70; Altium-Bottom: 50
footprint TXS0102DQE
pins: 1 B2, 2 GND, 3 VCCA, 4 A2, 5 A1, 6 OE, 7 VCCB, 8 B1

## TXS0102DQE_3
designator U?
Altium-Right: 70; Altium-Bottom: 50
footprint TXS0102DQE
pins: 1 B2, 2 GND, 3 VCCA, 4 A2, 5 A1, 6 OE, 7 VCCB, 8 B1

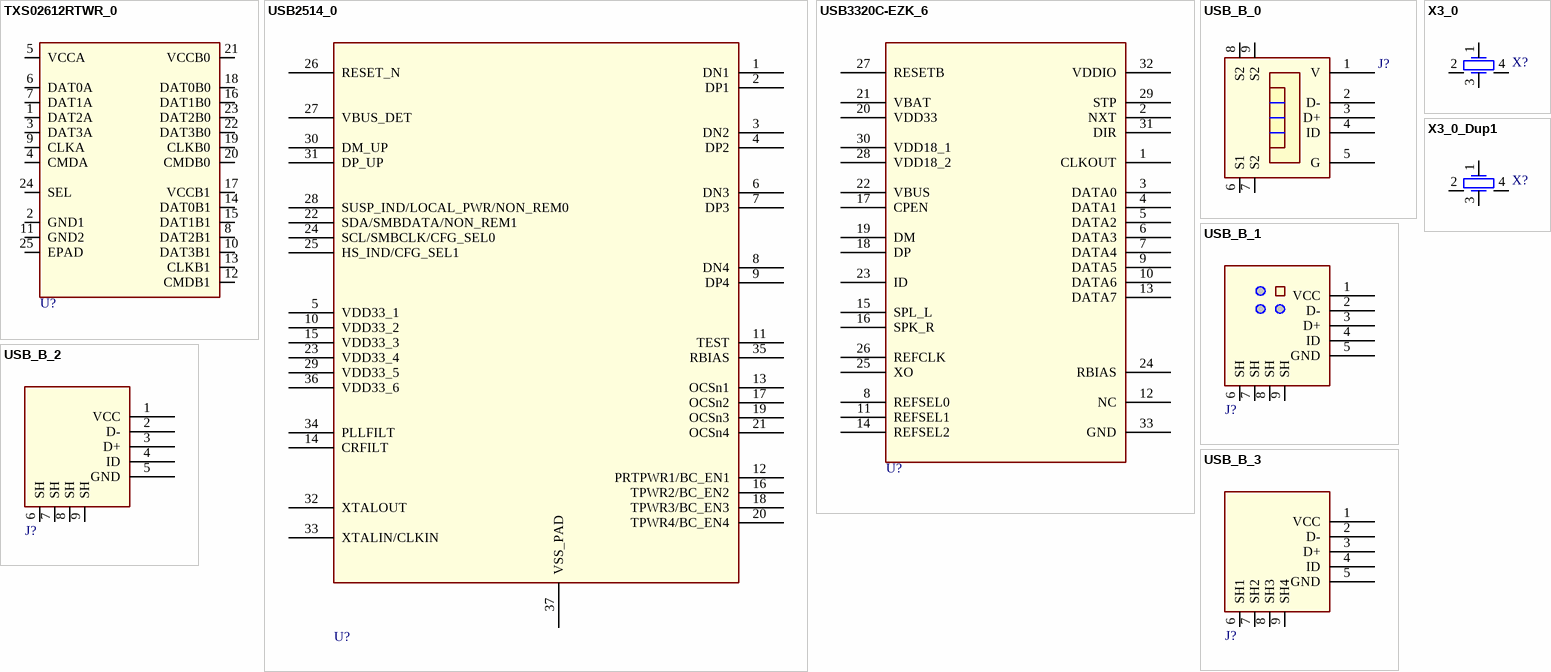
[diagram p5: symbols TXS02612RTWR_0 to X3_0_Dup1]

## TXS02612RTWR_0
designator U?
Altium-Right: 120; Altium-Bottom: 170
footprint QFN24_RTW
pins: 1 DAT2A, 2 GND1, 3 DAT3A, 4 CMDA, 5 VCCA, 6 DAT0A, 7 DAT1A, 8 DAT2B1, 9 CLKA, 10 DAT3B1, 11 GND2, 12 CMDB1, 13 CLKB1, 14 DAT0B1, 15 DAT1B1, 16 DAT1B0, 17 VCCB1, 18 DAT0B0, 19 CLKB0, 20 CMDB0, 21 VCCB0, 22 DAT3B0, 23 DAT2B0, 24 SEL, 25 EPAD

## USB2514_0
designator U?
Altium-Right: 270; Altium-Bottom: 360
footprint QFN-48
pins: 1 DN1, 2 DP1, 3 DN2, 4 DP2, 5 VDD33_1, 6 DN3, 7 DP3, 8 DN4, 9 DP4, 10 VDD33_2, 11 TEST, 12 PRTPWR1/BC_EN1, 13 OCSn1, 14 CRFILT, 15 VDD33_3, 16 TPWR2/BC_EN2, 17 OCSn2, 18 TPWR3/BC_EN3, 19 OCSn3, 20 TPWR4/BC_EN4, 21 OCSn4, 22 SDA/SMBDATA/NON_REM1, 23 VDD33_4, 24 SCL/SMBCLK/CFG_SEL0, 25 HS_IND/CFG_SEL1, 26 RESET_N, 27 VBUS_DET, 28 SUSP_IND/LOCAL_PWR/NON_REM0, 29 VDD33_5, 30 DM_UP, 31 DP_UP, 32 XTALOUT, 33 XTALIN/CLKIN, 34 PLLFILT, 35 RBIAS, 36 VDD33_6, 37 VSS_PAD

## USB3320C-EZK_6
designator U?
Altium-Right: 160; Altium-Bottom: 280
footprint USB3320C-EZK
pins: 1 CLKOUT, 2 NXT, 3 DATA0, 4 DATA1, 5 DATA2, 6 DATA3, 7 DATA4, 8 REFSEL0, 9 DATA5, 10 DATA6, 11 REFSEL1, 12 NC, 13 DATA7, 14 REFSEL2, 15 SPL_L, 16 SPK_R, 17 CPEN, 18 DP, 19 DM, 20 VDD33, 21 VBAT, 22 VBUS, 23 ID, 24 RBIAS, 25 XO, 26 REFCLK, 27 RESETB, 28 VDD18_2, 29 STP, 30 VDD18_1, 31 DIR, 32 VDDIO, 33 GND

## USB_B_0
designator J?
Altium-Right: 70; Altium-Bottom: 80
pins: 1 V, 2 D-, 3 D+, 4 ID, 5 G (power), 6 S1 (power), 7 S2 (power), 8 S2 (power), 9 S2 (power)

## USB_B_1
designator J?
Altium-Right: 70; Altium-Bottom: 80
pins: 1 VCC, 2 D-, 3 D+, 4 ID, 5 GND, 6 SH (power), 7 SH (power), 8 SH (power), 9 SH (power)

## USB_B_2
designator J?
Altium-Right: 70; Altium-Bottom: 80
pins: 1 VCC, 2 D-, 3 D+, 4 ID, 5 GND, 6 SH (power), 7 SH (power), 8 SH (power), 9 SH (power)

## USB_B_3
designator J?
Altium-Right: 70; Altium-Bottom: 80
pins: 1 VCC, 2 D-, 3 D+, 4 ID, 5 GND, 6 SH1 (power), 7 SH2 (power), 8 SH3 (power), 9 SH4 (power)

## X3_0
designator X?, comment X3  (value not drawn)
OriginalSymbolOrigin: (0,20); PKG_TYPE: XTAL2-200A; DEVICE: X_32768; CODE: 12020001; Altium-Right: 20; Altium-Bottom: 10
pins: 1 (io), 2, 3 (io), 4

## X3_0_Dup1
designator X?, comment X3  (value not drawn)
CODE: 12020001; DEVICE: X_32768; PKG_TYPE: XTAL2-200A; OriginalSymbolOrigin: (0,20); Altium-Right: 20; Altium-Bottom: 10
pins: 1 (io), 2 (io), 3 (io), 4 (io)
